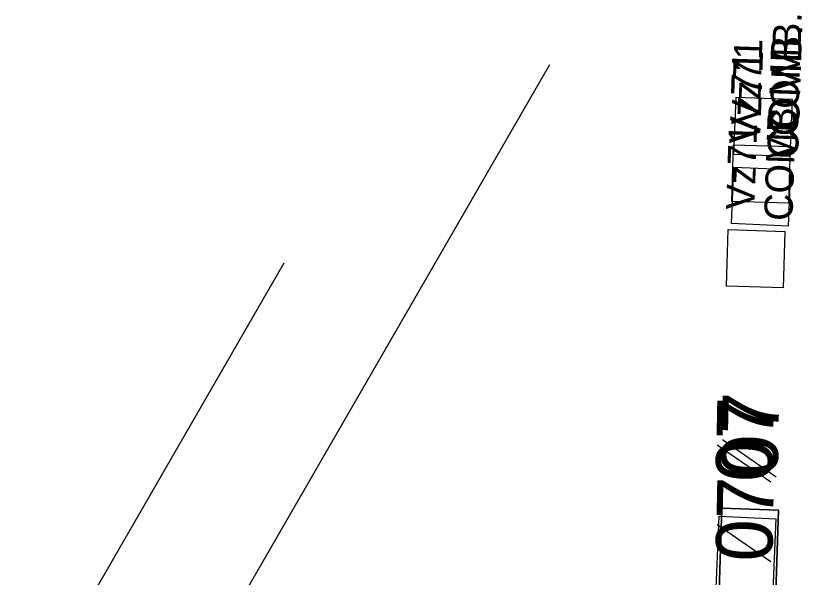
# Model space of a CAD drawing. Extents: x 647787 to 668496, y 640478 to 654412.
# Drawn here: x 662697.5 to 662780.9, y 647383.7 to 647443.2 of the extents above; entities that cross this region are included whole.
import ezdxf

# ---------------------------------------------------------------- set-up
doc = ezdxf.new("R2010")
doc.units = 0
for name, color, linetype in [('Default', 7, 'Continuous'), ('TEMP_DETECTION ZONE', 7, 'Continuous'), ('TEMP_DETECTION ZONE_Stage 2', 7, 'Continuous'), ('TEMP_DETECTION ZONE_STAGE 3', 7, 'Continuous'), ('TEMP_DETECTION_ZONE_STAGE 4', 7, 'Continuous'), ('TEMP_DETECTION_ZONE_STAGE 5', 7, 'Continuous'), ('TEMP_SIGNAL_POLES_STAGE 1B', 7, 'Continuous')]:
    doc.layers.add(name, color=color, linetype=linetype)

msp = doc.modelspace()

# ---------------------------------------------------------------- linework, layer by layer
at = {"layer": 'Default'}
for p, q in [((662772.432, 647398.316), (662778.109, 647394.376)), ((662772.432, 647398.316), (662778.109, 647394.376)), ((662772.432, 647398.316), (662778.109, 647394.376)), ((662772.432, 647398.316), (662778.109, 647394.376)), ((662772.432, 647398.316), (662778.109, 647394.376)), ((662772.432, 647398.316), (662778.109, 647394.376)), ((662772.432, 647398.316), (662778.109, 647394.376)), ((662772.432, 647398.316), (662778.109, 647394.376)), ((662771.867, 647397.781), (662777.545, 647393.84)), ((662771.867, 647389.345), (662777.545, 647385.405))]:
    msp.add_line(p, q, dxfattribs=at)
for points in [[(662754.084, 647438.004), (662703.768, 647350.872), (662536.704, 647412.118)], [(662725.933, 647417.005), (662675.617, 647329.874), (662508.553, 647391.119)], [(662725.933, 647417.005), (662675.617, 647329.874), (662508.553, 647391.119)], [(662725.933, 647417.005), (662675.617, 647329.874), (662508.553, 647391.119)]]:
    msp.add_lwpolyline(points, dxfattribs=at)
at = {"layer": 'TEMP_DETECTION ZONE'}
for points in [[(662773.836, 647434.53), (662773.588, 647428.535), (662779.585, 647428.338), (662779.832, 647434.333)], [(662773.836, 647434.53), (662773.588, 647428.535), (662779.585, 647428.338), (662779.832, 647434.333)], [(662770.711, 647341.082), (662776.708, 647340.885), (662778.352, 647390.858), (662772.355, 647391.055)], [(662770.711, 647341.082), (662776.708, 647340.885), (662778.352, 647390.858), (662772.355, 647391.055)]]:
    msp.add_lwpolyline(points, close=True, dxfattribs=at)
at = {"layer": 'TEMP_DETECTION ZONE_Stage 2'}
for points in [[(662779.395, 647423.344), (662773.398, 647423.541), (662773.595, 647429.538), (662779.592, 647429.34)], [(662776.71, 647340.887), (662770.713, 647341.084), (662772.357, 647391.057), (662778.354, 647390.86)]]:
    msp.add_lwpolyline(points, close=True, dxfattribs=at)
at = {"layer": 'TEMP_DETECTION ZONE_STAGE 3'}
for points in [[(662779.395, 647423.344), (662773.398, 647423.541), (662773.595, 647429.538), (662779.592, 647429.34)], [(662776.71, 647340.887), (662770.713, 647341.084), (662772.357, 647391.057), (662778.354, 647390.86)]]:
    msp.add_lwpolyline(points, close=True, dxfattribs=at)
at = {"layer": 'TEMP_DETECTION_ZONE_STAGE 4'}
for points in [[(662779.395, 647423.344), (662773.398, 647423.541), (662773.595, 647429.538), (662779.592, 647429.34)], [(662776.71, 647340.887), (662770.713, 647341.084), (662772.357, 647391.057), (662778.354, 647390.86)]]:
    msp.add_lwpolyline(points, close=True, dxfattribs=at)
at = {"layer": 'TEMP_DETECTION_ZONE_STAGE 5'}
msp.add_lwpolyline([(662778.83, 647414.373), (662772.833, 647414.57), (662773.031, 647420.567), (662779.027, 647420.369)], close=True, dxfattribs=at)
at = {"layer": 'TEMP_SIGNAL_POLES_STAGE 1B'}
for points in [[(662779.368, 647420.936), (662773.373, 647421.187), (662773.624, 647427.182), (662779.619, 647426.931)], [(662775.983, 647339.992), (662769.988, 647340.242), (662772.077, 647390.199), (662778.072, 647389.948)]]:
    msp.add_lwpolyline(points, close=True, dxfattribs=at)

# ---------------------------------------------------------------- texts
at = {"layer": 'Default'}
for p in [(662777.686, 647393.796), (662778.25, 647394.332), (662778.25, 647394.332), (662778.25, 647394.332), (662778.25, 647394.332), (662778.25, 647394.332), (662778.25, 647394.332), (662778.25, 647394.332), (662778.25, 647394.332), (662777.686, 647385.361)]:
    msp.add_text('07', height=6, rotation=88.82614, dxfattribs=at).set_placement(p)
at = {"layer": 'TEMP_DETECTION ZONE_Stage 2'}
for s, p in [('COMB.', (662780.383, 647430.409)), ('Vz71', (662776.356, 647431.593))]:
    msp.add_text(s, height=3, rotation=88.11574, dxfattribs=at).set_placement(p)
at = {"layer": 'TEMP_DETECTION ZONE_STAGE 3'}
for s, p in [('COMB.', (662780.383, 647430.409)), ('Vz71', (662776.356, 647431.593))]:
    msp.add_text(s, height=3, rotation=88.11574, dxfattribs=at).set_placement(p)
at = {"layer": 'TEMP_DETECTION_ZONE_STAGE 4'}
for s, p in [('COMB.', (662780.383, 647430.409)), ('Vz71', (662776.356, 647431.593))]:
    msp.add_text(s, height=3, rotation=88.11574, dxfattribs=at).set_placement(p)
at = {"layer": 'TEMP_DETECTION_ZONE_STAGE 5'}
for s, p in [('COMB.', (662779.818, 647421.438)), ('Vz71', (662775.791, 647422.622))]:
    msp.add_text(s, height=3, rotation=88.11574, dxfattribs=at).set_placement(p)
at = {"layer": 'TEMP_SIGNAL_POLES_STAGE 1B'}
for s, p in [('COMB.', (662780.41, 647428.022)), ('Vz71', (662776.391, 647429.588))]:
    msp.add_text(s, height=3.25, rotation=88.11574, dxfattribs=at).set_placement(p)

doc.saveas('drawing.dxf')
